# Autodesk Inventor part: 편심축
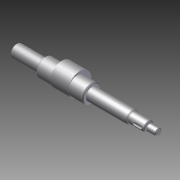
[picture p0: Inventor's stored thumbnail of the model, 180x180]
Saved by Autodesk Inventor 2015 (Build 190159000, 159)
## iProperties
Created: 2025-08
Part Number: 편심축
Material: 일반
Document SubType Name: Modeling
Designer: USER
Density: 1 g/cm^3
Appearance: 기본값
Author: USER
Author: jhkim
Creation Date: 2025-08-05
Sending System: Autodesk Inventor 2026
Preprocessor: ST-DEVELOPER v20.1
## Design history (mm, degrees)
node "편심축1"
node "솔리드1"
node "기준1"
